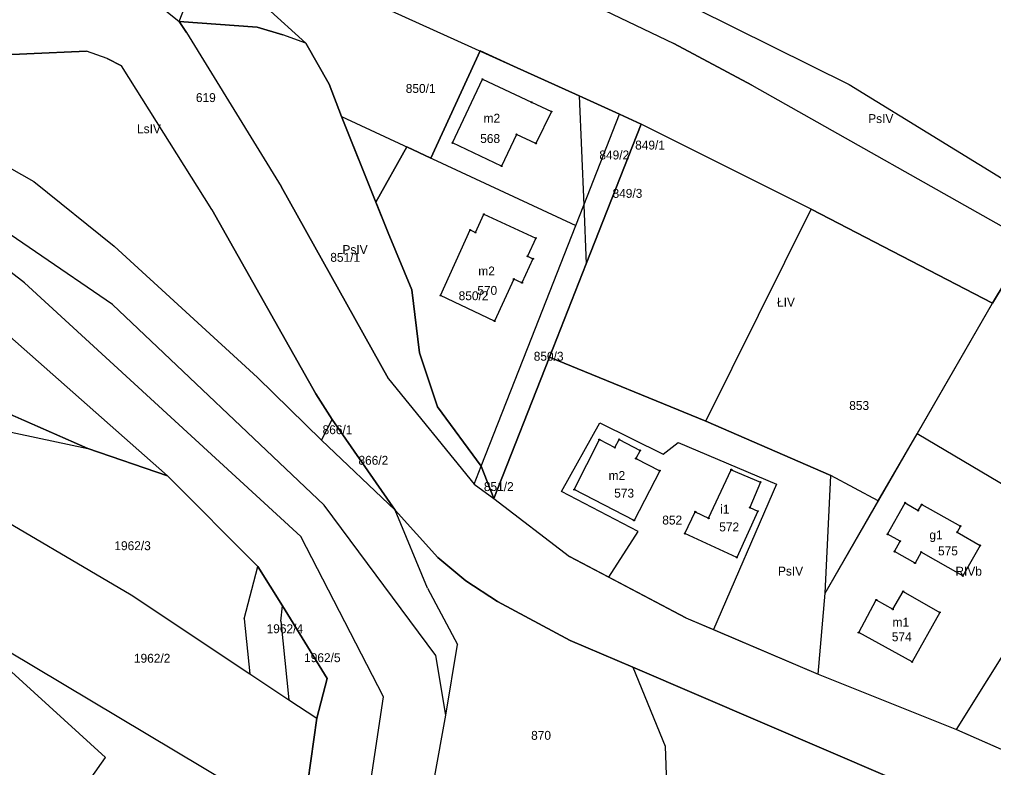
# Model space of a CAD drawing. Extents: x 7498273 to 7499989, y 5499795 to 5500810.
# Drawn here: x 7499569.7 to 7499733.8, y 5500097 to 5500223.1 of the extents above; entities that cross this region are included whole.
import ezdxf

# ---------------------------------------------------------------- set-up
doc = ezdxf.new("R2010")
doc.units = 0
for name, color, linetype in [('209-oznaczenie konturu klasyfikacyjnego', 7, 'Continuous'), ('211-numer działki ewidencyjnej', 7, 'Continuous'), ('217-kontur klasyfikacyjny', 7, 'Continuous'), ('218-kontur użytku gruntowego', 7, 'Continuous'), ('219-działka ewidencyjna', 7, 'Continuous'), ('312-budynek ewidencyjny', 7, 'Continuous'), ('312-oznaczenie budynku ewidencyjnego', 7, 'Continuous'), ('312-oznaczenie budynku ewidencyjnego-Atr117', 7, 'Continuous'), ('Punkt budynku', 7, 'Continuous')]:
    doc.layers.add(name, color=color, linetype=linetype)

# ---------------------------------------------------------------- blocks, each defined once
blk = doc.blocks.new('PUNKTBUD')
blk.add_circle((0, 0), 0.09)

msp = doc.modelspace()

# ---------------------------------------------------------------- linework, layer by layer
at = {"layer": '217-kontur klasyfikacyjny'}
for points in [[(7499638.25, 5500247.53), (7499709.49, 5500212.1)], [(7499640, 5500238.18), (7499679.94, 5500219.03)], [(7499591.75, 5500226.72), (7499596.65, 5500222.71)], [(7499596.65, 5500222.71), (7499597.84, 5500220.88)], [(7499609.77, 5500221.8), (7499596.65, 5500222.71)], [(7499597.84, 5500220.88), (7499613.83, 5500194.94)], [(7499614.08, 5500220.5), (7499609.77, 5500221.8)], [(7499617.95, 5500219.11), (7499614.08, 5500220.5)], [(7499621.89, 5500212.15), (7499617.95, 5500219.11)], [(7499679.94, 5500219.03), (7499693.1, 5500212)], [(7499581.01, 5500217.72), (7499560.83, 5500216.83)], [(7499584.5, 5500216.5), (7499581.01, 5500217.72)], [(7499639.03, 5500199.7), (7499647.31, 5500217.77)], [(7499647.31, 5500217.77), (7499652.96, 5500215.21)], [(7499586.91, 5500215.28), (7499584.5, 5500216.5)], [(7499602.11, 5500191.06), (7499586.91, 5500215.28)], [(7499652.96, 5500215.21), (7499663.98, 5500210.21)], [(7499623.96, 5500206.7), (7499621.89, 5500212.15)], [(7499693.1, 5500212), (7499739.84, 5500185.6)], [(7499709.49, 5500212.1), (7499757.83, 5500182.41)], [(7499663.98, 5500210.21), (7499670.81, 5500207.12)], [(7499629.75, 5500192.29), (7499623.96, 5500206.7)], [(7499670.81, 5500207.12), (7499674.45, 5500205.46)], [(7499556.34, 5500204.71), (7499572.13, 5500195.77)], [(7499674.45, 5500205.46), (7499665.2, 5500181.92)], [(7499703.08, 5500191.12), (7499674.45, 5500205.46)], [(7499629.75, 5500192.29), (7499634.96, 5500201.59)], [(7499634.96, 5500201.59), (7499639.03, 5500199.7)], [(7499572.13, 5500195.77), (7499585.65, 5500184.89)], [(7499613.83, 5500194.94), (7499631.87, 5500162.5)], [(7499619.65, 5500159.98), (7499602.11, 5500191.06)], [(7499631.83, 5500187.11), (7499629.75, 5500192.29)], [(7499733.63, 5500175.28), (7499703.08, 5500191.12)], [(7499635.8, 5500177.53), (7499631.83, 5500187.11)], [(7499585.65, 5500184.89), (7499609.83, 5500162.74)], [(7499739.84, 5500185.6), (7499733.63, 5500175.28)], [(7499665.2, 5500181.92), (7499659.02, 5500166.19)], [(7499594.67, 5500146.18), (7499559.32, 5500177.34)], [(7499637.1, 5500166.91), (7499635.8, 5500177.53)], [(7499720.92, 5500153.25), (7499733.63, 5500175.28)], [(7499640.15, 5500157.82), (7499637.1, 5500166.91)], [(7499659.02, 5500166.19), (7499649.6, 5500142.38)], [(7499685.34, 5500155.4), (7499659.02, 5500166.19)], [(7499609.83, 5500162.74), (7499620.61, 5500152.19)], [(7499631.87, 5500162.5), (7499646.29, 5500144.76)], [(7499622.4, 5500155.66), (7499619.65, 5500159.98)], [(7499581.25, 5500150.76), (7499563.43, 5500158.6)], [(7499647.5, 5500147.83), (7499640.15, 5500157.82)], [(7499633.02, 5500140.41), (7499622.4, 5500155.66)], [(7499661.05, 5500143.51), (7499667.49, 5500155.08)], [(7499667.49, 5500155.08), (7499678.15, 5500149.8)], [(7499706.4, 5500146.21), (7499685.34, 5500155.4)], [(7499714.39, 5500141.94), (7499720.92, 5500153.25)], [(7499748.5, 5500136.91), (7499720.92, 5500153.25)], [(7499620.61, 5500152.19), (7499633.02, 5500140.41)], [(7499678.15, 5500149.8), (7499680.7, 5500151.8)], [(7499680.7, 5500151.8), (7499697.25, 5500144.76)], [(7499594.67, 5500146.18), (7499581.25, 5500150.76)], [(7499649.6, 5500142.38), (7499647.5, 5500147.83)], [(7499609.86, 5500130.88), (7499594.67, 5500146.18)], [(7499714.39, 5500141.94), (7499706.4, 5500146.21)], [(7499646.29, 5500144.76), (7499649.6, 5500142.38)], [(7499673.95, 5500136.82), (7499661.05, 5500143.51)], [(7499697.25, 5500144.76), (7499686.61, 5500120.29)], [(7499649.6, 5500142.38), (7499662.37, 5500132.57)], [(7499705.44, 5500126.42), (7499714.39, 5500141.94)], [(7499669.01, 5500129.09), (7499673.95, 5500136.82)], [(7499662.37, 5500132.57), (7499669.01, 5500129.09)], [(7499614.02, 5500124.25), (7499609.86, 5500130.88)], [(7499704.26, 5500112.74), (7499705.44, 5500126.42)], [(7499621.58, 5500112.02), (7499614.02, 5500124.25)], [(7499558.19, 5500122.34), (7499610.05, 5500091.4)], [(7499727.54, 5500103.45), (7499738.44, 5500120.85)], [(7499686.61, 5500120.29), (7499704.26, 5500112.74)], [(7499673.05, 5500113.91), (7499678.51, 5500100.63)], [(7499716.31, 5500095.35), (7499673.05, 5500113.91)], [(7499704.26, 5500112.74), (7499727.54, 5500103.45)], [(7499619.81, 5500105.31), (7499621.58, 5500112.02)], [(7499617.27, 5500087.37), (7499619.81, 5500105.31)], [(7499678.51, 5500100.63), (7499678.8, 5500090.99)]]:
    msp.add_lwpolyline(points, dxfattribs=at)
at = {"layer": '218-kontur użytku gruntowego'}
for points in [[(7499638.25, 5500247.53), (7499709.49, 5500212.1)], [(7499640, 5500238.18), (7499679.94, 5500219.03)], [(7499591.75, 5500226.72), (7499596.65, 5500222.71)], [(7499596.65, 5500222.71), (7499597.84, 5500220.88)], [(7499609.77, 5500221.8), (7499596.65, 5500222.71)], [(7499597.84, 5500220.88), (7499613.83, 5500194.94)], [(7499614.08, 5500220.5), (7499609.77, 5500221.8)], [(7499617.95, 5500219.11), (7499614.08, 5500220.5)], [(7499621.89, 5500212.15), (7499617.95, 5500219.11)], [(7499679.94, 5500219.03), (7499693.1, 5500212)], [(7499581.01, 5500217.72), (7499560.83, 5500216.83)], [(7499584.5, 5500216.5), (7499581.01, 5500217.72)], [(7499647.31, 5500217.77), (7499639.03, 5500199.7)], [(7499652.96, 5500215.21), (7499647.31, 5500217.77)], [(7499586.91, 5500215.28), (7499584.5, 5500216.5)], [(7499602.11, 5500191.06), (7499586.91, 5500215.28)], [(7499663.98, 5500210.21), (7499652.96, 5500215.21)], [(7499623.96, 5500206.7), (7499621.89, 5500212.15)], [(7499693.1, 5500212), (7499739.84, 5500185.6)], [(7499709.49, 5500212.1), (7499757.83, 5500182.41)], [(7499670.81, 5500207.12), (7499663.98, 5500210.21)], [(7499629.75, 5500192.29), (7499623.96, 5500206.7)], [(7499674.45, 5500205.46), (7499670.81, 5500207.12)], [(7499556.34, 5500204.71), (7499572.13, 5500195.77)], [(7499665.2, 5500181.92), (7499674.45, 5500205.46)], [(7499703.08, 5500191.12), (7499674.45, 5500205.46)], [(7499634.96, 5500201.59), (7499629.75, 5500192.29)], [(7499639.03, 5500199.7), (7499634.96, 5500201.59)], [(7499572.13, 5500195.77), (7499585.65, 5500184.89)], [(7499613.83, 5500194.94), (7499631.87, 5500162.5)], [(7499585.41, 5500175.02), (7499559.4, 5500192.82)], [(7499619.65, 5500159.98), (7499602.11, 5500191.06)], [(7499631.83, 5500187.11), (7499629.75, 5500192.29)], [(7499733.63, 5500175.28), (7499703.08, 5500191.12)], [(7499570.55, 5500178.71), (7499560.29, 5500186.64)], [(7499635.8, 5500177.53), (7499631.83, 5500187.11)], [(7499585.65, 5500184.89), (7499609.83, 5500162.74)], [(7499739.84, 5500185.6), (7499733.63, 5500175.28)], [(7499659.02, 5500166.19), (7499665.2, 5500181.92)], [(7499617.14, 5500135.95), (7499570.55, 5500178.71)], [(7499559.32, 5500177.34), (7499594.67, 5500146.18)], [(7499637.1, 5500166.91), (7499635.8, 5500177.53)], [(7499621.02, 5500141.22), (7499585.41, 5500175.02)], [(7499720.92, 5500153.25), (7499733.63, 5500175.28)], [(7499640.15, 5500157.82), (7499637.1, 5500166.91)], [(7499649.6, 5500142.38), (7499659.02, 5500166.19)], [(7499685.34, 5500155.4), (7499659.02, 5500166.19)], [(7499609.83, 5500162.74), (7499620.61, 5500152.19)], [(7499631.87, 5500162.5), (7499646.29, 5500144.76)], [(7499622.4, 5500155.66), (7499619.65, 5500159.98)], [(7499581.25, 5500150.76), (7499563.43, 5500158.6)], [(7499647.5, 5500147.83), (7499640.15, 5500157.82)], [(7499633.02, 5500140.41), (7499622.4, 5500155.66)], [(7499661.05, 5500143.51), (7499667.49, 5500155.08)], [(7499667.49, 5500155.08), (7499678.15, 5500149.8)], [(7499706.4, 5500146.21), (7499685.34, 5500155.4)], [(7499714.39, 5500141.94), (7499720.92, 5500153.25)], [(7499748.5, 5500136.91), (7499720.92, 5500153.25)], [(7499620.61, 5500152.19), (7499633.02, 5500140.41)], [(7499678.15, 5500149.8), (7499680.7, 5500151.8)], [(7499680.7, 5500151.8), (7499697.25, 5500144.76)], [(7499594.67, 5500146.18), (7499581.25, 5500150.76)], [(7499649.6, 5500142.38), (7499647.5, 5500147.83)], [(7499594.67, 5500146.18), (7499609.86, 5500130.88)], [(7499714.39, 5500141.94), (7499706.4, 5500146.21)], [(7499646.29, 5500144.76), (7499649.6, 5500142.38)], [(7499673.95, 5500136.82), (7499661.05, 5500143.51)], [(7499697.25, 5500144.76), (7499686.61, 5500120.29)], [(7499649.6, 5500142.38), (7499662.37, 5500132.57)], [(7499705.44, 5500126.42), (7499714.39, 5500141.94)], [(7499639.84, 5500115.91), (7499621.02, 5500141.22)], [(7499640.17, 5500132.41), (7499633.02, 5500140.41)], [(7499669.01, 5500129.09), (7499673.95, 5500136.82)], [(7499631.03, 5500108.94), (7499617.14, 5500135.95)], [(7499644.91, 5500128.47), (7499640.17, 5500132.41)], [(7499662.37, 5500132.57), (7499669.01, 5500129.09)], [(7499609.86, 5500130.88), (7499614.02, 5500124.25)], [(7499669.01, 5500129.09), (7499681.99, 5500122.27)], [(7499650.23, 5500124.99), (7499644.91, 5500128.47)], [(7499704.26, 5500112.74), (7499705.44, 5500126.42)], [(7499614.02, 5500124.25), (7499621.58, 5500112.02)], [(7499662.48, 5500118.44), (7499650.23, 5500124.99)], [(7499558.19, 5500122.34), (7499610.05, 5500091.4)], [(7499681.99, 5500122.27), (7499686.61, 5500120.29)], [(7499727.54, 5500103.45), (7499738.44, 5500120.85)], [(7499686.61, 5500120.29), (7499704.26, 5500112.74)], [(7499673.05, 5500113.91), (7499662.48, 5500118.44)], [(7499641.56, 5500105.84), (7499639.84, 5500115.91)], [(7499673.05, 5500113.91), (7499678.51, 5500100.63)], [(7499716.31, 5500095.35), (7499673.05, 5500113.91)], [(7499704.26, 5500112.74), (7499727.54, 5500103.45)], [(7499621.58, 5500112.02), (7499619.81, 5500105.31)], [(7499626.85, 5500080.91), (7499631.03, 5500108.94)], [(7499637.62, 5500084.15), (7499641.56, 5500105.84)], [(7499619.81, 5500105.31), (7499617.27, 5500087.37)], [(7499727.54, 5500103.45), (7499751.15, 5500093.04)], [(7499678.51, 5500100.63), (7499678.8, 5500090.99)]]:
    msp.add_lwpolyline(points, dxfattribs=at)
at = {"layer": '219-działka ewidencyjna'}
for points in [[(7499640, 5500238.18), (7499679.94, 5500219.03)], [(7499607.01, 5500236.03), (7499652.96, 5500215.21)], [(7499604.8, 5500231.05), (7499617.95, 5500219.11)], [(7499596.65, 5500222.71), (7499598.76, 5500228.23)], [(7499591.75, 5500226.72), (7499596.65, 5500222.71)], [(7499597.84, 5500220.88), (7499596.65, 5500222.71)], [(7499596.65, 5500222.71), (7499609.77, 5500221.8)], [(7499597.84, 5500220.88), (7499613.83, 5500194.94)], [(7499609.77, 5500221.8), (7499614.08, 5500220.5)], [(7499617.95, 5500219.11), (7499614.08, 5500220.5)], [(7499617.95, 5500219.11), (7499621.89, 5500212.15)], [(7499693.1, 5500212), (7499679.94, 5500219.03)], [(7499560.83, 5500216.83), (7499581.01, 5500217.72)], [(7499584.5, 5500216.5), (7499581.01, 5500217.72)], [(7499584.5, 5500216.5), (7499586.91, 5500215.28)], [(7499602.11, 5500191.06), (7499586.91, 5500215.28)], [(7499663.98, 5500210.21), (7499652.96, 5500215.21)], [(7499621.89, 5500212.15), (7499623.96, 5500206.7)], [(7499693.1, 5500212), (7499739.84, 5500185.6)], [(7499663.98, 5500210.21), (7499664.78, 5500191.76)], [(7499663.98, 5500210.21), (7499670.81, 5500207.12)], [(7499623.96, 5500206.7), (7499631.83, 5500187.11)], [(7499623.96, 5500206.7), (7499663.43, 5500188.36)], [(7499664.78, 5500191.76), (7499670.81, 5500207.12)], [(7499670.81, 5500207.12), (7499674.45, 5500205.46)], [(7499556.34, 5500204.71), (7499572.13, 5500195.77)], [(7499665.2, 5500181.92), (7499674.45, 5500205.46)], [(7499572.13, 5500195.77), (7499585.65, 5500184.89)], [(7499631.87, 5500162.5), (7499613.83, 5500194.94)], [(7499602.11, 5500191.06), (7499619.65, 5500159.98)], [(7499663.43, 5500188.36), (7499664.78, 5500191.76)], [(7499664.78, 5500191.76), (7499665.2, 5500181.92)], [(7499685.34, 5500155.4), (7499703.08, 5500191.12)], [(7499703.08, 5500191.12), (7499733.63, 5500175.28)], [(7499655.27, 5500167.61), (7499663.43, 5500188.36)], [(7499631.83, 5500187.11), (7499635.8, 5500177.53)], [(7499585.65, 5500184.89), (7499609.83, 5500162.74)], [(7499733.63, 5500175.28), (7499739.84, 5500185.6)], [(7499659.02, 5500166.19), (7499665.2, 5500181.92)], [(7499559.32, 5500177.34), (7499594.67, 5500146.18)], [(7499635.8, 5500177.53), (7499637.1, 5500166.91)], [(7499705.44, 5500126.42), (7499733.63, 5500175.28)], [(7499637.1, 5500166.91), (7499640.15, 5500157.82)], [(7499647.5, 5500147.83), (7499655.27, 5500167.61)], [(7499649.6, 5500142.38), (7499659.02, 5500166.19)], [(7499659.02, 5500166.19), (7499685.34, 5500155.4)], [(7499553.41, 5500163.01), (7499581.25, 5500150.76)], [(7499609.83, 5500162.74), (7499620.61, 5500152.19)], [(7499631.87, 5500162.5), (7499646.29, 5500144.76)], [(7499619.65, 5500159.98), (7499622.4, 5500155.66)], [(7499640.15, 5500157.82), (7499647.5, 5500147.83)], [(7499620.61, 5500152.19), (7499622.4, 5500155.66)], [(7499622.4, 5500155.66), (7499633.02, 5500140.41)], [(7499685.34, 5500155.4), (7499706.4, 5500146.21)], [(7499563.78, 5500154.5), (7499581.25, 5500150.76)], [(7499620.61, 5500152.19), (7499633.02, 5500140.41)], [(7499581.25, 5500150.76), (7499594.67, 5500146.18)], [(7499646.29, 5500144.76), (7499647.5, 5500147.83)], [(7499647.5, 5500147.83), (7499649.6, 5500142.38)], [(7499594.67, 5500146.18), (7499609.86, 5500130.88)], [(7499705.44, 5500126.42), (7499706.4, 5500146.21)], [(7499646.29, 5500144.76), (7499649.6, 5500142.38)], [(7499561.56, 5500141.98), (7499588.52, 5500126.12)], [(7499649.6, 5500142.38), (7499662.37, 5500132.57)], [(7499638.48, 5500127.27), (7499633.02, 5500140.41)], [(7499640.17, 5500132.41), (7499633.02, 5500140.41)], [(7499727.54, 5500103.45), (7499748.5, 5500136.91)], [(7499640.17, 5500132.41), (7499644.91, 5500128.47)], [(7499681.99, 5500122.27), (7499662.37, 5500132.57)], [(7499607.59, 5500122.05), (7499609.86, 5500130.88)], [(7499609.86, 5500130.88), (7499614.02, 5500124.25)], [(7499638.48, 5500127.27), (7499643.5, 5500117.73)], [(7499644.91, 5500128.47), (7499650.23, 5500124.99)], [(7499588.52, 5500126.12), (7499608.55, 5500112.8)], [(7499704.26, 5500112.74), (7499705.44, 5500126.42)], [(7499613.75, 5500121.67), (7499614.02, 5500124.25)], [(7499614.02, 5500124.25), (7499621.58, 5500112.02)], [(7499650.23, 5500124.99), (7499662.48, 5500118.44)], [(7499558.19, 5500122.34), (7499584.23, 5500098.69)], [(7499558.19, 5500122.34), (7499610.05, 5500091.4)], [(7499607.59, 5500122.05), (7499608.55, 5500112.8)], [(7499681.99, 5500122.27), (7499704.26, 5500112.74)], [(7499613.75, 5500121.67), (7499615.11, 5500108.44)], [(7499641.56, 5500105.84), (7499643.5, 5500117.73)], [(7499662.48, 5500118.44), (7499673.05, 5500113.91)], [(7499673.05, 5500113.91), (7499716.31, 5500095.35)], [(7499673.05, 5500113.91), (7499678.51, 5500100.63)], [(7499608.55, 5500112.8), (7499615.11, 5500108.44)], [(7499704.26, 5500112.74), (7499727.54, 5500103.45)], [(7499619.81, 5500105.31), (7499621.58, 5500112.02)], [(7499615.11, 5500108.44), (7499619.81, 5500105.31)], [(7499637.62, 5500084.15), (7499641.56, 5500105.84)], [(7499617.27, 5500087.37), (7499619.81, 5500105.31)], [(7499727.54, 5500103.45), (7499769.73, 5500084.85)], [(7499678.51, 5500100.63), (7499678.8, 5500090.99)], [(7499562.42, 5500067.86), (7499584.23, 5500098.69)]]:
    msp.add_lwpolyline(points, dxfattribs=at)
at = {"layer": '312-budynek ewidencyjny'}
for points in [[(7499642.65, 5500202.27), (7499647.7, 5500213)], [(7499647.7, 5500213), (7499655.99, 5500209.12)], [(7499655.99, 5500209.12), (7499659.32, 5500207.56)], [(7499659.32, 5500207.56), (7499656.72, 5500202.2)], [(7499653.44, 5500203.7), (7499650.93, 5500198.38)], [(7499656.72, 5500202.2), (7499653.44, 5500203.7)], [(7499650.93, 5500198.38), (7499642.65, 5500202.27)], [(7499646.54, 5500187.19), (7499647.95, 5500190.26)], [(7499647.95, 5500190.26), (7499656.72, 5500186.24)], [(7499640.64, 5500176.57), (7499645.63, 5500187.61)], [(7499645.63, 5500187.61), (7499646.54, 5500187.19)], [(7499656.72, 5500186.24), (7499655.31, 5500183.17)], [(7499656.22, 5500182.75), (7499654.37, 5500178.72)], [(7499655.31, 5500183.17), (7499656.22, 5500182.75)], [(7499652.98, 5500179.34), (7499649.75, 5500172.26)], [(7499654.37, 5500178.72), (7499652.98, 5500179.34)], [(7499649.75, 5500172.26), (7499640.64, 5500176.57)], [(7499663.18, 5500143.85), (7499667.4, 5500152.29)], [(7499667.4, 5500152.29), (7499670.02, 5500150.94)], [(7499670.02, 5500150.94), (7499670.72, 5500152.3)], [(7499670.72, 5500152.3), (7499674.27, 5500150.46)], [(7499674.27, 5500150.46), (7499673.57, 5500149.1)], [(7499673.57, 5500149.1), (7499677.57, 5500147.04)], [(7499677.57, 5500147.04), (7499673.24, 5500138.66)], [(7499685.81, 5500139.03), (7499689.63, 5500147.21)], [(7499689.63, 5500147.21), (7499694.54, 5500145.11)], [(7499694.54, 5500145.11), (7499692.75, 5500140.83)], [(7499673.24, 5500138.66), (7499663.18, 5500143.85)], [(7499681.8, 5500136.44), (7499683.56, 5500140.11)], [(7499683.56, 5500140.11), (7499685.81, 5500139.03)], [(7499694.11, 5500140.21), (7499690.56, 5500132.43)], [(7499692.75, 5500140.83), (7499694.11, 5500140.21)], [(7499715.96, 5500136.33), (7499718.92, 5500141.62)], [(7499718.92, 5500141.62), (7499721.09, 5500140.33)], [(7499721.09, 5500140.33), (7499721.7, 5500141.32)], [(7499721.7, 5500141.32), (7499728.21, 5500137.71)], [(7499728.21, 5500137.71), (7499727.66, 5500136.67)], [(7499690.56, 5500132.43), (7499681.8, 5500136.44)], [(7499718.07, 5500135.15), (7499715.96, 5500136.33)], [(7499717.11, 5500133.42), (7499718.07, 5500135.15)], [(7499727.66, 5500136.67), (7499731.56, 5500134.44)], [(7499731.56, 5500134.44), (7499728.63, 5500129.31)], [(7499720.57, 5500131.48), (7499717.11, 5500133.42)], [(7499721.6, 5500133.32), (7499720.57, 5500131.48)], [(7499728.63, 5500129.31), (7499721.6, 5500133.32)], [(7499716.82, 5500123.68), (7499718.57, 5500126.71)], [(7499718.57, 5500126.71), (7499724.74, 5500123.16)], [(7499711.08, 5500119.76), (7499714.05, 5500125.27)], [(7499714.05, 5500125.27), (7499716.82, 5500123.68)], [(7499724.74, 5500123.16), (7499720.1, 5500114.81)], [(7499720.1, 5500114.81), (7499711.08, 5500119.76)]]:
    msp.add_lwpolyline(points, dxfattribs=at)

# ---------------------------------------------------------------- block references
at = {"layer": 'Punkt budynku'}
for p in [(7499647.7, 5500213), (7499655.99, 5500209.12), (7499659.32, 5500207.56), (7499653.44, 5500203.7), (7499642.65, 5500202.27), (7499656.72, 5500202.2), (7499650.93, 5500198.38), (7499647.95, 5500190.26), (7499645.63, 5500187.61), (7499646.54, 5500187.19), (7499656.72, 5500186.24), (7499655.31, 5500183.17), (7499656.22, 5500182.75), (7499652.98, 5500179.34), (7499654.37, 5500178.72), (7499640.64, 5500176.57), (7499649.75, 5500172.26), (7499667.4, 5500152.29), (7499670.72, 5500152.3), (7499670.02, 5500150.94), (7499674.27, 5500150.46), (7499673.57, 5500149.1), (7499677.57, 5500147.04), (7499689.63, 5500147.21), (7499694.54, 5500145.11), (7499663.18, 5500143.85), (7499718.92, 5500141.62), (7499683.56, 5500140.11), (7499692.75, 5500140.83), (7499694.11, 5500140.21), (7499721.09, 5500140.33), (7499721.7, 5500141.32), (7499673.24, 5500138.66), (7499685.81, 5500139.03), (7499728.21, 5500137.71), (7499681.8, 5500136.44), (7499715.96, 5500136.33), (7499718.07, 5500135.15), (7499727.66, 5500136.67), (7499717.11, 5500133.42), (7499731.56, 5500134.44), (7499690.56, 5500132.43), (7499721.6, 5500133.32), (7499720.57, 5500131.48), (7499728.63, 5500129.31), (7499714.05, 5500125.27), (7499718.57, 5500126.71), (7499716.82, 5500123.68), (7499724.74, 5500123.16), (7499711.08, 5500119.76), (7499720.1, 5500114.81)]:
    msp.add_blockref('PUNKTBUD', p, dxfattribs=at)

# ---------------------------------------------------------------- texts
at = {"layer": '209-oznaczenie konturu klasyfikacyjnego'}
for s, p in [('PsIV', (7499712.69, 5500205.62)), ('LsIV', (7499589.53, 5500203.91)), ('PsIV', (7499624.13, 5500183.55)), ('ŁIV', (7499697.33, 5500174.7)), ('PsIV', (7499697.49, 5500129.37)), ('RIVb', (7499727.38, 5500129.35))]:
    msp.add_text(s, height=1.5, dxfattribs=at).set_placement(p)
at = {"layer": '211-numer działki ewidencyjnej'}
for s, p in [('850/1', (7499634.79, 5500210.7)), ('619', (7499599.44, 5500209.16)), ('849/1', (7499673.43, 5500201.16)), ('849/2', (7499667.4, 5500199.49)), ('849/3', (7499669.62, 5500193.02)), ('851/1', (7499622.08, 5500182.24)), ('850/2', (7499643.7, 5500175.77)), ('850/3', (7499656.35, 5500165.57)), ('853', (7499709.49, 5500157.27)), ('866/1', (7499620.78, 5500153.19)), ('866/2', (7499626.82, 5500148.04)), ('851/2', (7499647.95, 5500143.61)), ('852', (7499678, 5500137.97)), ('1962/3', (7499585.71, 5500133.65)), ('1962/4', (7499611.35, 5500119.66)), ('1962/2', (7499589, 5500114.68)), ('1962/5', (7499617.67, 5500114.78)), ('870', (7499655.91, 5500101.69))]:
    msp.add_text(s, height=1.5, dxfattribs=at).set_placement(p)
at = {"layer": '312-oznaczenie budynku ewidencyjnego'}
for s, p in [('568', (7499647.33, 5500202.26)), ('570', (7499646.84, 5500176.67)), ('573', (7499669.9, 5500142.51)), ('572', (7499687.59, 5500136.81)), ('575', (7499724.45, 5500132.77)), ('574', (7499716.66, 5500118.3))]:
    msp.add_text(s, height=1.5, dxfattribs=at).set_placement(p)
at = {"layer": '312-oznaczenie budynku ewidencyjnego-Atr117'}
for s, p in [('m2', (7499647.906, 5500205.69)), ('m2', (7499647.016, 5500179.94)), ('m2', (7499668.966, 5500145.48)), ('i1', (7499687.752, 5500139.82)), ('g1', (7499722.989, 5500135.47)), ('m1', (7499716.785, 5500120.76))]:
    msp.add_text(s, height=1.5, dxfattribs=at).set_placement(p)

doc.saveas('drawing.dxf')
